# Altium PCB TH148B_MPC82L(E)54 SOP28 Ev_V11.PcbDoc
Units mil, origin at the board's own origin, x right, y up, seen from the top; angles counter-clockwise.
Board outline 2850 x 2110 mil, 2 copper layers (Top Layer, Bottom Layer); 44 components, 47 nets, 236 pads, 94 vias.
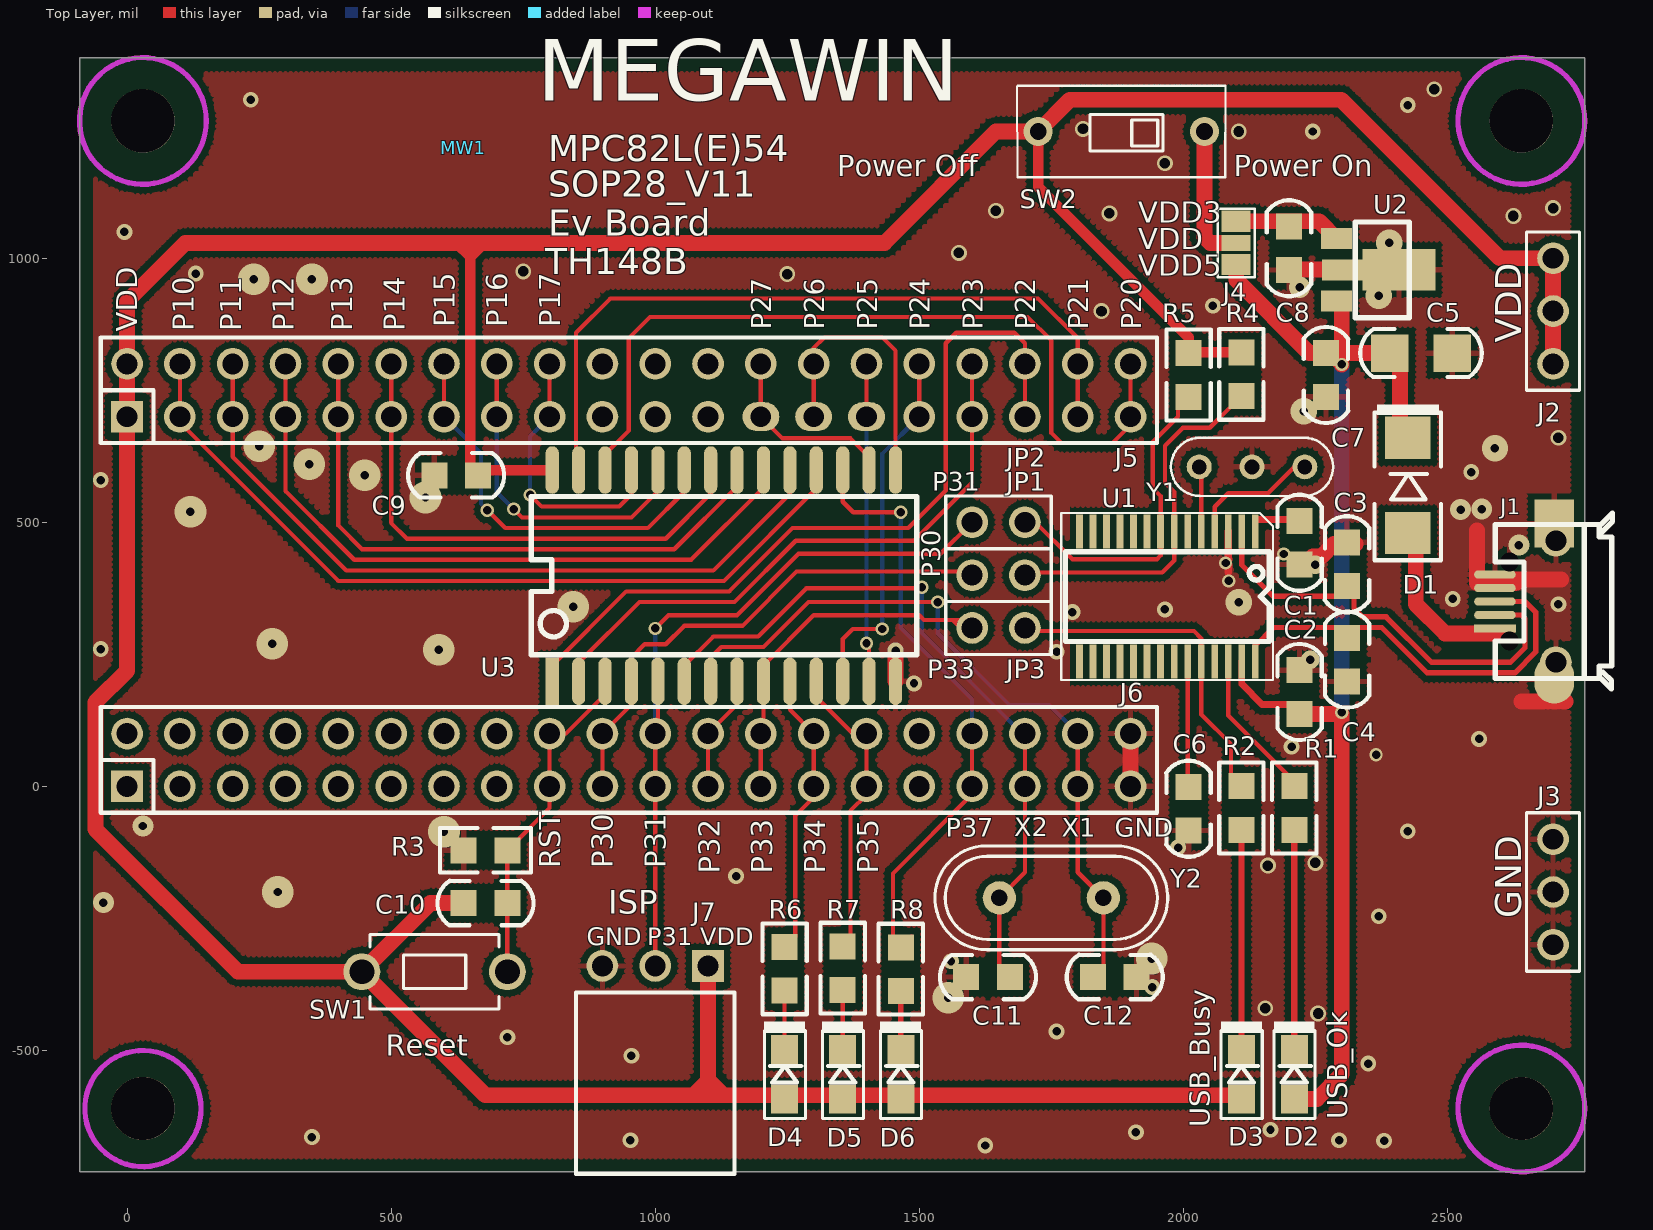
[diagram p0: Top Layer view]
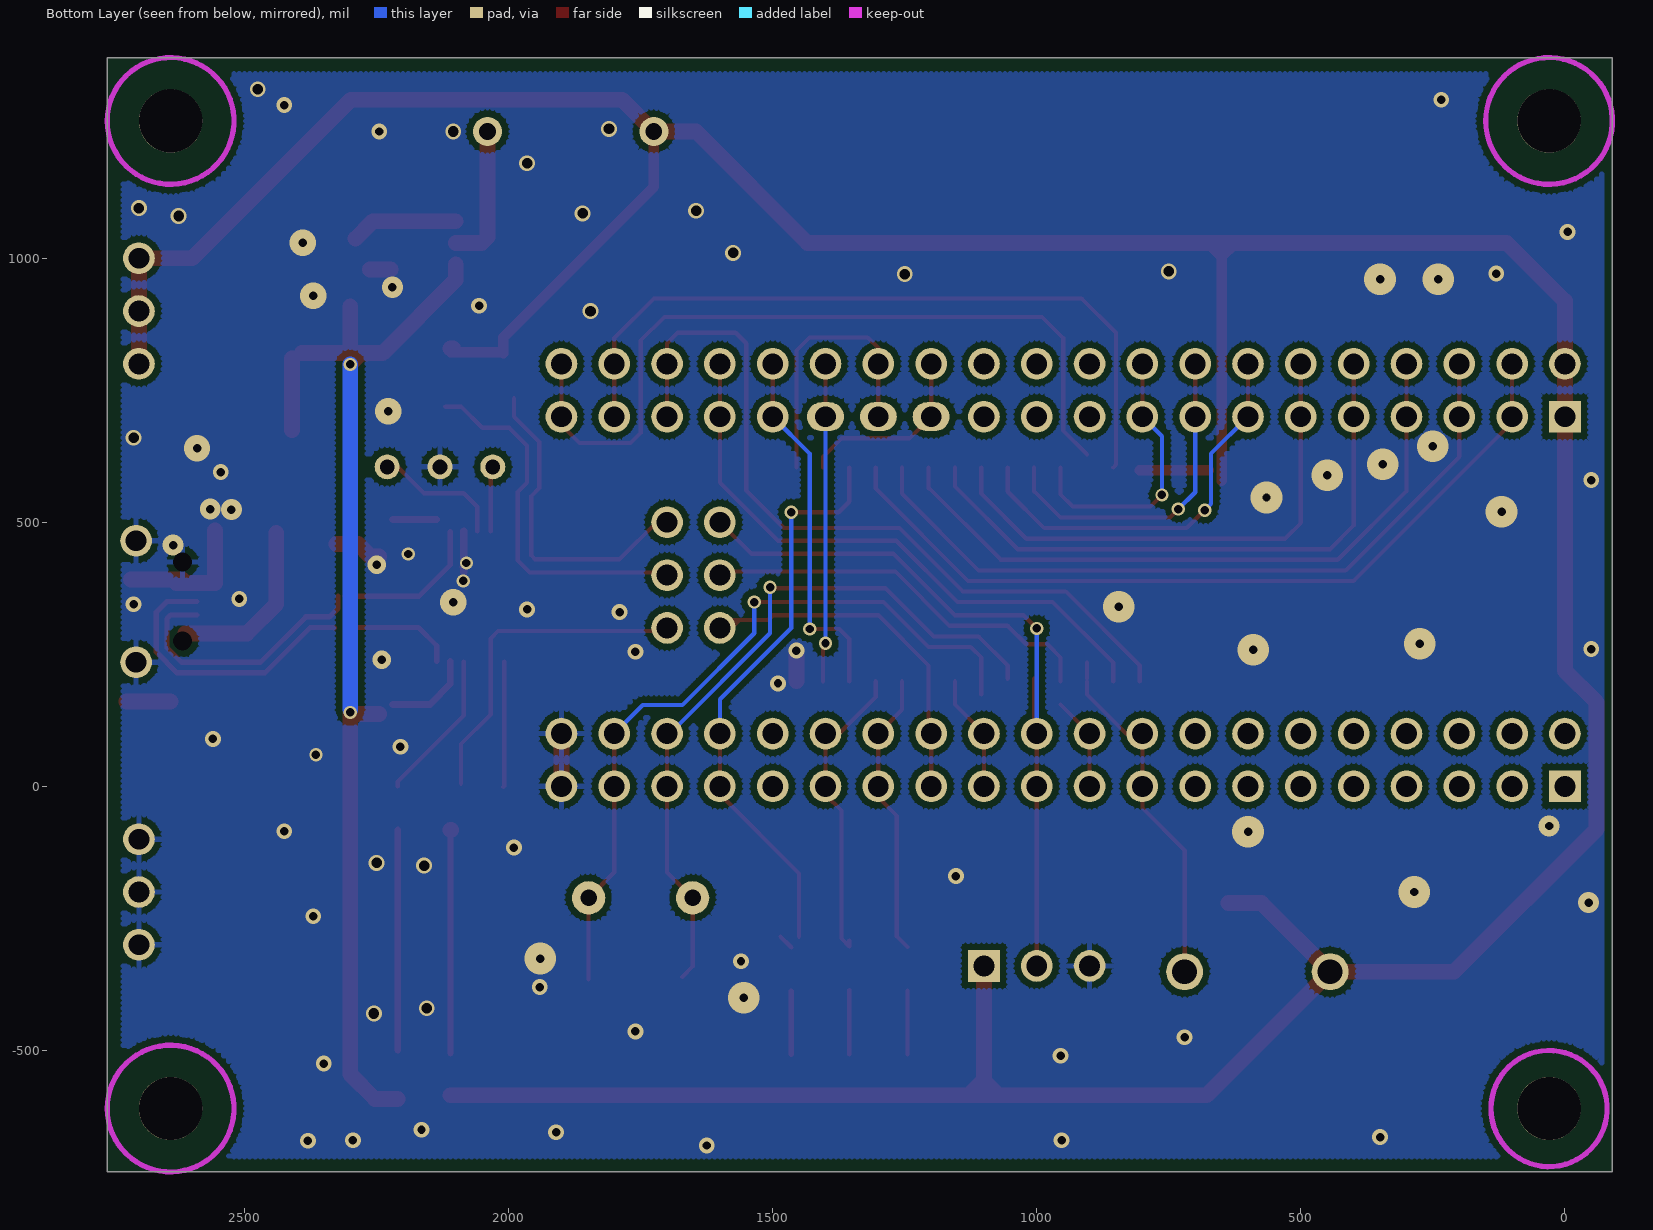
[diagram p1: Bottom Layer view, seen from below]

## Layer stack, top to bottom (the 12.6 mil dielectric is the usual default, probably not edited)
Top Layer: signal copper 1.4
Dielectric: dielectric 12.6, FR-4, Dk 4.8
Bottom Layer: signal copper 1.4

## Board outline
-90,-730 -90,1380 2760,1380 2760,-730

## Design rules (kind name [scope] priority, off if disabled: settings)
Clearance 12 [All] p1 off: gap=12
Clearance 10 [All] p2 off: gap=10
Clearance 6 [All] p3: gap=6
ComponentClearance [All] p1 off: gap=10 collisioncheckmode=3 verticalgap=10 showdistances=FALSE
HoleSize [All] p1: absolutevalues=TRUE maxlimit=500 minlimit=1 maxpercent=80.000 minpercent=20.000
MinimumSolderMaskSliver [All] p1 off: minsoldermaskwidth=10
PolygonConnect VIA [ISVIA] p1: connectstyle=Direct reliefconductorwidth=10 reliefentries=4 polygonreliefangle="90 Angle"
PolygonConnect [All] p2: connectstyle=Relief reliefconductorwidth=10 reliefentries=4 polygonreliefangle="90 Angle"
RoomDefinition "TH148B_MPC82L(E)54 SOP28 Ev_V101" [InComponentClass('TH148B_MPC82L(E)54 SOP28 Ev_V101')] p1: confinementstyle=ConfineIn formatcopy=TRUE lockcomponents=FALSE outline -190,-805 3060,-805 3060,1445 -190,1445
RoutingVias [All] p1: holewidth=16 width=25 viastyle="Through Hole" minholewidth=16 minwidth=24 maxholewidth=28 maxwidth=50
SilkToSilkClearance [All] p1 off: silktosilkclearance=10
SilkscreenOverComponentPads [All] p1 off: minsilkscreentomaskgap=10
SolderMaskExpansion [All] p1 off: expansion=4
Width [All] p1: maxlimit=200 minlimit=6 preferedwidth=10
23 further rules are at their usual default settings.

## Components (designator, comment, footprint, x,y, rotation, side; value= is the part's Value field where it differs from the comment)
C1 "4.7uF" 0805C 2220,461.34 r270 top
C2 "0.1uF" 0805C 2220,178.66 r270 top
C3 "15pF" 0805C 2310,420.71 r90 top
C4 "15pF" 0805C 2310,240 r270 top
C5 "4.7uF" 1206C 2450,820.34 r0 top
C6 "0.1uF" 0805C 2010,-42.34 r90 top
C7 "0.1uF" 0805C 2270,779 r270 top
C8 "4.7uF" 0805C 2200,1019 r270 top
C9 "0.1uF" 0805C 623,589 r180 top
C10 "1u" 0805C 678.66,-221 r0 top
C11 "30pF" 0805C 1630,-361 r180 top
C12 "30pF" 0805C 1870,-361 r0 top
D1 "1N5817" D5817_SMD_1 2425,570 r270 top
D2 "Yellow" 0805D 2210,-545 r90 top
D3 "RED" 0805D 2110,-545 r90 top
D4 "Green" 0805D 1245,-545 r90 top
D5 "RED" 0805D 1355,-545 r90 top
D6 "Green" 0805D 1465,-545 r90 top
J1 "Micro USB母座" JACK_USB_SMD290X220P065 2590,350 r180 top
J2 "*" PS3P254 2700,800 r90 top
J3 "*" PS3P254 2700,-100 r270 top
J4 "*" JUMP3_SMD 2100,1029 r90 top
J5 "*" PS20X2P254#1 0,700 r0 top locked
J6 "*" PS20X2P254#2 0,0 r0 top locked
J7 "*" PS3P254f_90 1100,-340 r180 top
JP1 "JUMPER2" PS2P254 1600,400 r0 top
JP2 "JUMPER2" PS2P254 1600,500 r0 top
JP3 "JUMPER2" PS2P254 1600,300 r0 top
MW1 "MW-A4" MEGAWIN_T 636.19,1209.19 r0 top
R1 "1K" 0805R 2210,-41 r270 top
R2 "1K" 0805R 2110,-41 r270 top
R3 "47K" 0805R 678.66,-121 r0 top
R4 "4.7K" 0805R 2110,780.34 r270 top
R5 "4.7K" 0805R 2010,779 r270 top
R6 "1K" 0805R 1245,-345.42 r270 top
R7 "1K" 0805R 1355,-344.08 r270 top
R8 "1K" 0805R 1465,-346 r270 top
SW1 "SW TACT-SPST" SW_T_2P 582.21,-351 r0 top
SW2 "-" DIP2_SW 2040,1240 r180 top
U1 "MA101_TSSOP28" TSSOP28_170P065 1969.84,359.52 r180 top
U2 "AIC1734-33(SOT-89)" SOT89 2290,978.06 r270 top
U3 "MPC82L54(SOP-28)" SO28_300P127 1130,399 r0 top locked
Y1 "6MHz" X3P 2230,605 r180 top (schematic designator X1)
Y2 "22.1184MHz" X49U 1750,-211 r0 top (schematic designator X2)

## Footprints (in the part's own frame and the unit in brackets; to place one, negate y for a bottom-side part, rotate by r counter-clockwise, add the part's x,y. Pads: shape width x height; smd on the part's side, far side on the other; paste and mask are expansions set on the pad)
0805C [mm]
  rect 1.25x1.25 smd: 1(-1.05,0) 2(1.05,0)
  silkscreen extent -2.31,-1.07 2.31,1.07
0805D [mm]
  rect 1.4x1.3 smd: 1(-1.192,0) 2(1.192,0)
  silkscreen extent -2.12,-1 2.53,0.98
0805R [mm]
  rect 1.25x1.25 smd: 1(-1.05,0) 2(1.05,0)
  silkscreen extent -2.18,-1.07 2.18,1.07
1206C [mm]
  rect 1.8x1.8 smd: 1(-1.5,0) 2(1.5,0)
  silkscreen extent -2.92,-1.15 2.92,1.16
D5817_SMD_1 [mil]
  rect 80x86.61 smd: 1(90,0) 2(-90,0)
  silkscreen extent -153,-63 142,63
DIP2_SW [mm]
  round 1.4 hole 0.8: 1(0,0) 2(8,0)
  silkscreen extent -1.02,-2.2 9.02,2.2
JACK_USB_SMD290X220P065 [mm]
  rect 1.9x1.8 on Mech2: 0(-2.85,-1.15) 0(-2.85,1.15)
  round 0.8 hole 0.9 unplated: 1(-0.7,1.9) 5(-0.7,-1.9)
  rect 2x0.4 smd: 1(0,1.3)
  oval 2x0.4 smd: 2(0,0.65) 3(0,0) 4(0,-0.65) 5(0,-1.3)
  round 1.524 hole 1: 5(-2.931,2.921) 5(-2.931,-2.921)
  oval 1.9x2.3 smd: 5(-2.85,3.75)
  rect 1.9x2.3 smd: 5(-2.85,-3.75)
  silkscreen extent -5.65,-4.25 -0.01,4.2
JUMP3_SMD [mil]
  rect 40x55 smd: 1(-41,0) 3(41,0)
  rect 30x55 smd: 2(0,0)
  silkscreen extent -65,-35 65,35
MEGAWIN_T [mil]
PS2P254 [mil]
  round 60 hole 39.37: 1(0,0) 2(100,0)
  silkscreen extent -50,-50 150,50
PS3P254 [mil]
  round 60 hole 39.37: 1(0,0) 2(100,0) 3(200,0)
  silkscreen extent -50,-50 250,50
PS3P254f_90 [mil]
  rect 60x60 hole 39.37: 1(0,0)
  round 60 hole 39.37: 2(100,0) 3(200,0)
  silkscreen extent -50,50 250,394
PS20X2P254#1 [mil]
  rect 60x60 hole 39.37: 1(0,0)
  round 60 hole 39.37: 2(0,100) 3(100,0) 4(100,100) 5(200,0) 6(200,100) 7(300,0) 8(300,100) 9(400,0) 10(400,100) 11(500,0) 12(500,100) 13(600,0) 14(600,100) 15(700,0) 16(700,100) 17(800,0) 18(800,100) 19(900,0) 20(900,100) 21(1000,0) 22(1000,100) 23(1100,0) 24(1100,100) 26(1200,100) 28(1300,100) 30(1400,100) 31(1500,0) 32(1500,100) 33(1600,0) 34(1600,100) 35(1700,0) 36(1700,100) 37(1800,0) 38(1800,100) 39(1900,0) 40(1900,100)
  oval 70x55 hole 39.37: 25(1200,0) 27(1300,0) 29(1400,0)
  silkscreen extent -50,-50 1950,150
PS20X2P254#2 [mil]
  rect 60x60 hole 39.37: 1(0,0)
  round 60 hole 39.37: 2(0,100) 3(100,0) 4(100,100) 5(200,0) 6(200,100) 7(300,0) 8(300,100) 9(400,0) 10(400,100) 11(500,0) 12(500,100) 13(600,0) 14(600,100) 15(700,0) 16(700,100) 17(800,0) 18(800,100) 19(900,0) 20(900,100) 21(1000,0) 22(1000,100) 23(1100,0) 24(1100,100) 25(1200,0) 26(1200,100) 27(1300,0) 28(1300,100) 29(1400,0) 30(1400,100) 31(1500,0) 32(1500,100) 33(1600,0) 34(1600,100) 35(1700,0) 36(1700,100) 37(1800,0) 38(1800,100) 39(1900,0) 40(1900,100)
  silkscreen extent -50,-50 1950,150
SO28_300P127 [mil]
  rect 25x90 smd: 1(-325,-200)
  oval 25x90 smd: 2(-275,-200) 3(-225,-200) 4(-175,-200) 5(-125,-200) 6(-75,-200) 7(-25,-200) 8(25,-200) 9(75,-200) 10(125,-200) 11(175,-200) 12(225,-200) 13(275,-200) 14(325,-200) 15(325,200) 16(275,200) 17(225,200) 18(175,200) 19(125,200) 20(75,200) 21(25,200) 22(-25,200) 23(-75,200) 24(-125,200) 25(-175,200) 26(-225,200) 27(-275,200) 28(-325,200)
  silkscreen extent -365,-150 365,150
SOT89 [mm]
  rect 1.016x1.5 smd: 1(-1.5,0) 3(1.5,0)
  rect 2x3.5 smd: 2(0,3)
  rect 1.016x2.6 smd: 2(0,0.6)
  silkscreen extent -2.3,0.9 2.3,3.5
SW_T_2P [mil]
  round 70 hole 47.24: 1(-137.79,0) 2(137.79,0)
  silkscreen extent -122,-71 122,71
TSSOP28_170P065 [mil]
  rect 13x65 smd: 1(-166.34,-123) 2(-140.75,-123) 3(-115.16,-123) 4(-89.57,-123) 5(-63.98,-123) 6(-38.39,-123) 7(-12.79,-123) 8(12.8,-123) 9(38.39,-123) 10(63.98,-123) 11(89.57,-123) 12(115.16,-123) 13(140.75,-123) 14(166.34,-123) 15(166.34,123) 16(140.75,123) 17(115.16,123) 18(89.57,123) 19(63.98,123) 20(38.39,123) 21(12.8,123) 22(-12.79,123) 23(-38.39,123) 24(-63.98,123) 25(-89.57,123) 26(-115.16,123) 27(-140.75,123) 28(-166.34,123)
  silkscreen extent -200,-158 201,158
X3P [mm]
  round 1.2 hole 0.711: 1(0,0) 2(5.08,0) 3(2.54,0)
  silkscreen extent -1.36,-1.4 6.44,1.4
X49U [mm]
  round 1.6 hole 0.8: 1(-2.5,0) 2(2.5,0)
  silkscreen extent -5.6,-2.5 5.6,2.5

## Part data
C1 C5 C8: library part CAP
C2 C3 C4 C6 C7 C9: library part "CAP NP"
C10: library part C
C11 C12: library part "C NP"
D1: library part DIODE_ZD, "Schottky Diode"
D2 D3 D4 D5 D6: library part LED
J1: library part CON5, "Connector"
J2 J3 J4 J7: library part CON3
J5 J6: library part CON40A
R1 R2 R4 R5 R6 R7 R8: library part R_Dup1
R3: library part R
SW2: library part SW-2
U2: library part AIC1734-33(SOT-89)_0
U3: library part MPC82L54(TSSOP28)
Y1: library part CRYSTAL_RC
Y2: library part CRYSTAL

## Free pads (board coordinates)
  round 120 hole 120 unplated: 0(30,-610) 0(30,1260) 0(2640,-610) 0(2640,1260)

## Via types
v1: diameter 30, hole 16, Top Layer to Bottom Layer, tented both sides, 35 vias
v2: diameter 30, hole 20, Top Layer to Bottom Layer, tented both sides, 17 vias
v3: diameter 25, hole 16, Top Layer to Bottom Layer, tented both sides, 15 vias
v4: diameter 60, hole 16, Top Layer to Bottom Layer, tented both sides, 14 vias
v5: diameter 50, hole 16, Top Layer to Bottom Layer, tented both sides, 5 vias
v6: diameter 40, hole 16, Top Layer to Bottom Layer, tented both sides, 4 vias
v7: diameter 39.37, hole 16, Top Layer to Bottom Layer, tented both sides, 2 vias
v8: diameter 35, hole 16, Top Layer to Bottom Layer, tented both sides, 2 vias

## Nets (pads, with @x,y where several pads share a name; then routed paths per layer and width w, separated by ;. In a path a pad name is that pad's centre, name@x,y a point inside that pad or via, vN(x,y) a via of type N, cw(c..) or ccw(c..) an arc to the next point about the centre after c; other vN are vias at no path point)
D+: C4.1 J1.3 U1.28 | length 763.5
  Top Layer w10: U1.28 2136.18,266.18 2171,301 C4.1@2305.33,301 ; C4.1@2330,300 2331,301 2375.72,301 2461.72,215 2627.72,215 2667,254.28 2667,329.93 2646.93,350 J1.3
D-: C3.1 J1.2 U1.2 | length 802.9
  Top Layer w10: U1.2 2110.59,419.25 2169.84,360 C3.1@2310,360 ; C3.1@2323,360 2323,337 2339,321 2384,321 2470,235 2619.44,235 2647,262.56 2647,317.84 2640.43,324.41 J1.2
GND_POWER: C1.2 C2.1 C3.2 C4.2 C5.2 C6.1 C7.2 C8.2 C9.2 C11.2 C12.2 J1.4 J1.5 J3.1 J3.2 J3.3 J6.39 J6.40 J7.3 R3.1 U1.3 U2.2 U3.14 Y1.3 | length 718
  Top Layer w15: 2085,406 v3@2085,416 ; U1.3 2085,423 v3@2085,416 ; v3@2086,415 v3@2085,416
  Top Layer w30: U3.14 v1(1455,257) ; J6.39 J6.40 ; C8.2@2223.34,979 U2.2@2263,979 ; v8@2245,435 2250,435 2261,435 2285,459 2310,459 C3.2@2326.32,459 ; 2555.87,385.05 2590,385.05 2629.29,385.05 ; 2555.87,387.64 2555.87,401.18 2555.87,484.72 ; 2618.54,392.05 2715.63,392.05 ; 2640.28,160.87 2702.2,160.87 2723.82,160.87
  other v1: 1625,-680 2380,-671 953,-670 2295,-670 350,-664 1910,-655 2165,-650 2350,-525 955,-510 720,-475 1760,-464 1941,-380 1560,-331 2370,-246 1153,-170 1990,-116 2425,-85 2205,75 2560,90 1490,195 1760,255 -50,260 1790,330 1965,335 2710,345 2510,355 -50,580 2545,595 2056,910 130,971 -5,1050 2245,1240 2425,1290 234,1300
  other v2: 2255,-430 2155,-420 2160,-150 2250,-145 2710,660 1845,900 1250,970 750,975 1575,1010 2625,1080 1860,1085 1645,1090 2700,1095 1965,1180 2105,1240 1810,1245 2475,1320
  other v3: 2365,60 2086,389 2080,423 2190,440
  other v4: 1555,-400 1940,-326 285,-200 600,-86 590,259 275,270 845,340 120,520 565,547 450,589 345,610 250,644 240,960 350,960
  other v5: 2105,349 2590,640 2228,710.5 2370,929 2390,1029
  other v6: -45,-220 30,-75 2635.29,456.72 2220,945
  other v7: 2525,524 2565,525
  other v8: 2240,240 2250,420
MA101_RX: JP2.2 R5.2 U1.8 | length 613
  Top Layer w8: JP2.2 1720,500 1790,430 1950,430 1957.05,437.05 U1.8 1957.05,550 1942.05,565 1942.05,652.05 1990,700 R5.2@1990,735
MA101_TX: JP1.2 R4.2 U1.7 | length 697.3
  Top Layer w8: JP1.2@1705,405 1960,405 1982.64,427.64 U1.7 1982.64,557.36 1965,575 1965,645 1999,679 2050,679 2090,719 2110,719 R4.2@2120,719
NetC1_1: C1.1 U1.1 | length 83.8
  Top Layer w13: U1.1@2136.18,505 C1.1@2220,505
NetC6_2: C6.2 U1.23 | length 287.7
  Top Layer w8: 2008.23,141.77 2008.23,179 ; 2008.23,191.18 2008.23,179 ; U1.23 2008.23,179 ; C6.2 2008.23,0.77 2008.23,179
NetD1_1: D1.1 J1.1 | length 330.1
  Top Layer w30: D1.1@2440,480 2440,345 2495.28,289.72 2590,289.72 J1.1@2612.2,289.72
NetD2_2: D2.2 R1.2 | length 417.7
  Top Layer w12: D2.2@2210,-500 D2.2 R1.2
NetD3_2: D3.2 R2.2 | length 422.1
  Top Layer w12: D3.2@2110,-505 D3.2 R2.2@2110,-84.26
  Top Layer w30: R2.2@2108.66,-82.34 R2.2
NetD4_2: D4.2 R6.2 | length 120.4
  Top Layer w8: D4.2@1245,-507.16 D4.2 R6.2
NetD5_2: D5.2 R7.2 | length 121.7
  Top Layer w8: D5.2@1355,-507.16 D5.2 R7.2
NetD6_2: D6.2 R8.2 | length 119.8
  Top Layer w10: D6.2@1465,-507.16 D6.2 R8.2
NetJ4_2: J4.2 SW2.1 | length 264.6
  Top Layer w30: SW2.1 2040,1040 2051,1029 J4.2
NetU1_4: U1.4 Y1.1 | length 248.8
  Top Layer w8: U1.4 2059.41,529.41 2085,555 2160,555 2210,605 Y1.1
NetU1_5: U1.5 Y1.2 | length 127.1
  Top Layer w8: Y1.2@2018.82,593.82 Y1.2 ; U1.5 Y1.2@2033.82,593.82
P10: J5.3 J5.4 U3.18 | length 1552.8
  Top Layer w8: J5.4 J5.3 100,689 400,389 1130,389 1305,564 U3.18 U3.18@1305,604
P11: J5.5 J5.6 U3.19 | length 1430.1
  Top Layer w8: J5.6 J5.5 200,624 415,409 1110,409 1255,554 U3.19 U3.19@1255,604
P12: J5.7 J5.8 U3.20 | length 1296.6
  Top Layer w8: J5.8 J5.7 300,559 430,429 1068,429 U3.20@1205,566 ; U3.20@1205,564 U3.20@1205,566 ; U3.20@1205,604 U3.20 U3.20@1205,566
P13: J5.9 J5.10 U3.21 | length 1164.9
  Top Layer w8: J5.10 J5.9 400,494 445,449 1036,449 1155,568 U3.21 U3.21@1155,604
P14: J5.11 J5.12 U3.22 | length 1003.6
  Top Layer w8: J5.12 J5.11 500,499 530,469 1020,469 1105,554 U3.22 U3.22@1105,604
P15: J5.13 J5.14 U3.23 | length 772.6
  Top Layer w8: J5.13 J5.14 ; v3(682,523) 716,489 986,489 1055,558 U3.23 U3.23@1055,604
  Bottom Layer w8: J5.13 670,630 670,535 v3(682,523)
P16: J5.15 J5.16 U3.24 | length 633.6
  Top Layer w8: J5.15 J5.16 ; v3(732,525) 748,509 955,509 1005,559 U3.24 U3.24@1005,604
  Bottom Layer w8: J5.15 700,557 v3(732,525)
P17: J5.17 J5.18 U3.25 | length 525
  Top Layer w8: v3(763,552) 785,530 932,530 955,553 U3.25 U3.25@955,604 ; J5.17 J5.18
  Bottom Layer w8: v3(763,552) 763,663 J5.17
P20: J5.39 J5.40 U3.26 | length 1536.8
  Top Layer w8: U3.26@905,629 950,674 950,849 990,889 1705,889 1750,844 1750,669 1769,650 1866,650 1900,684 J5.39 J5.40
P21: J5.37 J5.38 U3.27 | length 1414.1
  Top Layer w8: U3.27@855,604 850,609 850,859 915,924 1725,924 1800,849 J5.38 J5.37
P22: J5.35 J5.36 U3.1 | length 1496.7
  Top Layer w8: U3.1 805,229 945,369 1140,369 1260,489 1479,489 1550,560 1550,839 1570,859 1680,859 1700,839 J5.36 J5.35
P23: J5.33 J5.34 U3.2 | length 1166.3
  Top Layer w8: U3.2 855,234 970,349 1150,349 1266,465 1490,465 1600,575 J5.33 J5.34 J5.34@1585.79,785.79
P24: J5.31 J5.32 U3.12 | length 715.1
  Top Layer w8: U3.12 1355,279 1374,298 v3(1430,298) ; J5.31 J5.32
  Bottom Layer w8: v3(1430,298) 1430,630 J5.31 J5.31@1485,685
P25: J5.29 J5.30 U3.13 | length 601
  Top Layer w8: J5.29 J5.30 ; U3.13 v3@1405,271
  Bottom Layer w8: v3(1400,271) J5.29
P26: J5.27 J5.28 U3.15 | length 524.6
  Top Layer w8: J5.27 J5.28 1300,830 1320,850 1430,850 1455,825 U3.15@1455,604
P27: J5.25 J5.26 U3.16 | length 356.5
  Top Layer w8: J5.26 J5.25 1241,659 1370,659 1405,624 U3.16@1405,604
P30_RXD: J6.19 J6.20 JP1.1 U3.4 | length 926.8
  Top Layer w8: J6.19 J6.20 ; J6.20@909.46,109.46 U3.4@955,155 ; U3.4@955,204 U3.4 955,244 980,269 1020,269 1055,304 1165,304 1267.69,406.69 JP1.1@1600,406.69
P31_TXD: J6.21 J6.22 J7.2 JP2.1 U3.5 | length 1422.3
  Top Layer w8: J7.2@1000,-341 J7.2 J6.21 J6.22 ; v3(1000,299) 1025,324 1155,324 1271.38,440.38 1540.38,440.38 JP2.1 ; J6.22@1005,105 U3.5 U3.5@1005,204
  Bottom Layer w8: J6.22 v3(1000,299)
P32: J6.23 J6.24 U3.8 | length 221.8
  Top Layer w8: J6.23 J6.24 1155,155 U3.8
P33: J6.25 J6.26 JP3.1 U3.9 | length 711.8
  Top Layer w8: J6.25 J6.26 1205,105 U3.9 1205,229 1300,324 1500,324 1509,315 1563,315 ; JP3.1@1579,299 1563,315 ; JP3.1@1620,315 1600,315 1563,315
P34: J6.27 J6.28 R6.1 U3.10 | length 544.5
  Top Layer w8: R6.1 1265,-284.08 1265,-56 1300,-21 J6.27 J6.28 1255,145 U3.10
P35: J6.29 J6.30 R7.1 U3.11 | length 585.7
  Top Layer w8: U3.11 1305,169 1374,100 J6.30 J6.29 1400,-16 1370,-46 1370,-287.74 R7.1 R7.1@1355,-292
P37: J6.33 J6.34 R8.1 U3.17 | length 1134.2
  Top Layer w8: U3.17@1355,604 U3.17 1355,539 1375,519 v3(1465,519) ; R8.1@1450,-284.66 1450,-164.82 ; 1450.18,-164.82 1600,-15 J6.33 J6.34 ; R8.1 R8.1@1485,-284.66
  Bottom Layer w8: v3@1460,519 v3@1462.5,516.5 ; v3@1465,516.5 1465,300 1600,165 J6.34
RST: C10.2 J6.17 J6.18 R3.2 SW1.2 U3.3 | length 643.8
  Top Layer w8: SW1.2 C10.2 R3.2 800,-41 J6.17 J6.18 ; 831,100 905,174 U3.3 ; U3.3@905,204 U3.3@905,234
USB_BUSY: JP3.2 R2.1 U1.24 | length 682
  Top Layer w8: JP3.2@1706,294 1955,294 ; 1995,294 1955,294 ; 2010,294 2020,294 ; R2.1@2090,5 2090,80 2033.82,136.18 U1.24 2033.82,280.18 2020,294 ; 1955,294 2020,294
USB_OK: R1.1 U1.26 | length 288
  Top Layer w8: U1.26 2085,134 2210,9 R1.1
VDD: C9.1 C10.1 D3.1 D4.1 D5.1 D6.1 J2.1 J2.2 J2.3 J5.1 J5.2 J7.1 R4.1 R5.1 SW1.1 SW2.2 U3.28 | length 8495.6
  Top Layer w15: 613,1034 618,1029 ; 618.5,1030.5 620,1029 650,999 680,1029 681,1030 ; 681,1029 686,1034 ; 1062,-584.9 1099,-547.9 ; 1103,-547.9 1140,-584.9
  Top Layer w20: C9.1@650,579 650,589 650,999 650,1019 ; C9.1@674.34,599 U3.28 ; SW2.2 1725,1135 2010,850 R5.1 ; R5.1@2011.34,821.68 R4.1
  Top Layer w30: C10.1 574.41,-221 SW1.1 ; J7.1@1100,-341 1100,-584.9 ; SW2.2 1645.04,1240 1434.04,1029 681,1029 680,1029 620,1029 618,1029 110,1029 0,919 J5.2 J5.1 0,219 -60,159 -60,-81 210,-351 SW1.1 ; SW2.2 1785.04,1300 2299,1300 2599,1000 J2.3 J2.2 J2.1 ; R4.1@2104.95,829 R4.1@2110,829 ; D3.1@2110,-584.9 1465,-584.9 1355,-584.9 1245,-584.9 1140,-584.9 1100,-584.9 ; SW1.1 678.31,-584.9 1062,-584.9 1100,-584.9
VDD3: C8.1 J4.3 U2.1 | length 203.6
  Top Layer w30: J4.3 2200,1070 2257.11,1070 U2.1
VDD5: C2.2 C5.1 C7.1 D1.2 D2.1 J4.1 U1.27 U2.3 | length 2300.8
  Top Layer w13: U1.27 2110.59,193.41 2149,155 C2.2@2220,155
  Top Layer w30: J4.1 2100,959 2238.66,820.34 C7.1@2268.66,820.34 ; D2.1 2253.08,-591.92 2300,-545 2300,137.32 2245,137.32 ; C7.1@2269.33,819.67 C7.1@2268.66,820.34 ; v3(2300,799) 2300,800.34 C7.1@2280,820.34 ; U2.3@2300,909 2300,820.34 ; C5.1 2300,820.34 ; D1.2@2410,675 C5.1@2410,810 ; C7.1@2268.66,820.34 C7.1 C7.1@2280,820.34 ; C7.1@2280,820.34 2300,820.34
  Bottom Layer w30: v3@2300,145 v3(2300,799)
  other v3: 2300,140
XTAL1: C12.1 J6.37 J6.38 U3.7 Y2.2 | length 1461.3
  Top Layer w8: U3.7@1105,174 U3.7 ; U3.7@1105,204 U3.7 ; v3(1535,349) 1290,349 1205,264 1125,264 1105,244 U3.7 ; J6.38 J6.37 1800,-162.58 Y2.2 1848.66,-211.24 1848.66,-361 C12.1@1848.66,-365
  Bottom Layer w8: 1535,310 1535,335 ; v3(1535,349) 1535,335 ; J6.38 1746.1,153.9 1671.1,153.9 1535,290 1535,335
XTAL2: C11.1 J6.35 J6.36 U3.6 Y2.1 | length 1381.3
  Top Layer w8: U3.6@1055,204 1055,229 1110,284 1195,284 1286,375 v3@1505,375 ; C11.1 1651.57,-341.24 Y2.1 1700,-162.58 J6.35 J6.36
  Bottom Layer w8: v3@1505,375 1505,290 1690,105 J6.36@1700,105
  other v3: 1505,377
pads on no net: J1.0 J5.19 J5.20 J5.21 J5.22 J5.23 J5.24 J6.1 J6.2 J6.3 J6.4 J6.5 J6.6 J6.7 J6.8 J6.9 J6.10 J6.11 J6.12 J6.13 J6.14 J6.15 J6.16 J6.31 J6.32 U1.6 U1.9 U1.10 U1.11 U1.12 U1.13 U1.14 U1.15 U1.16 U1.17 U1.18 U1.19 U1.20 U1.21 U1.22 U1.25

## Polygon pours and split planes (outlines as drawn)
GND_POWER on Bottom Layer "Bottom Layer-No Net" (hatched 90Degree grid 10 track 10, remove dead copper, pour order 1001): -70,-701 2730,-701 2730,1350 -70,1350
GND_POWER on Top Layer "Bottom Layer-No Net" (hatched 90Degree grid 10 track 10, remove dead copper, pour order 1001): -60,-701 2730,-701 2730,1350 -60,1350

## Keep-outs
Keep-Out Layer:
  circle w10: c2640,-610 r120
  circle w10: c30,1260 r120
  circle w10: c30,-610 r110
  circle w10: c2640,1260 r120

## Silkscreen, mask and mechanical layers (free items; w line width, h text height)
Top Overlay:
  text "MPC82L(E)54" at 797,1184 h50
  text "Power Off" at 1345,1155 h40
  text "Power On" at 2095,1155 h40
  text "SOP28_V11" at 797,1116 h50
  text "VDD3" at 1914.25,1067 h40
  text "Ev Board" at 797,1043 h50
  text "VDD" at 1914.25,1017 h40
  text "TH148B" at 792,970 h50
  text "VDD5" at 1914.25,967 h40
  text "P15" at 619.95,868.95 h40 r90
  text "P16" at 719.95,868.95 h40 r90
  text "P17" at 819.95,868.95 h40 r90
  text "P27" at 1220,865 h38 r90
  text "P26" at 1320,865 h38 r90
  text "P25" at 1420,865 h38 r90
  text "P24" at 1520,865 h38 r90
  text "P23" at 1620,865 h38 r90
  text "P22" at 1720,865 h38 r90
  text "P21" at 1820,865 h38 r90
  text "P20" at 1920,865 h38 r90
  text "P10" at 126,862 h40 r90
  text "P11" at 216,862 h40 r90
  text "P12" at 316,862 h40 r90
  text "P13" at 426,862 h40 r90
  text "P14" at 526,862 h40 r90
  text "VDD" at 19,861 h40 r90
  text "VDD" at 2640,840 h50 r90
  text "P31" at 1525,560 h35
  text "P30" at 1540,395 h35 r90
  text "P33" at 1515,205 h35
  text "X2" at 1680,-94 h35
  text "P37" at 1550,-95 h35
  text "X1" at 1770,-95 h35.43
  text "GND" at 1870,-95 h35.43
  text "RST" at 820,-155 h40 r90
  text "P30" at 920,-155 h40 r90
  text "P31" at 1020,-155 h40 r90
  text "P32" at 1122,-165 h40 r90
  text "P33" at 1222,-165 h40 r90
  text "P34" at 1322,-165 h40 r90
  text "P35" at 1422,-165 h40 r90
  text "ISP" at 911,-241 h45
  text "GND" at 2640,-250 h50 r90
  text "GND" at 870,-301 h33
  text "P31" at 985,-301 h33
  text "VDD" at 1085,-301 h33
  text "Reset" at 490,-510 h40
  text "USB_Ok" at 2310,-630 h38 r90
  text "USB_Busy" at 2050,-645 h38 r90
Mechanical 1:
  the board outline again, w13

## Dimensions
-90,-730 to 2760,-730 on Top Overlay
-90,1380 to -90,-730 on Top Overlay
